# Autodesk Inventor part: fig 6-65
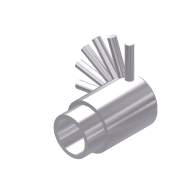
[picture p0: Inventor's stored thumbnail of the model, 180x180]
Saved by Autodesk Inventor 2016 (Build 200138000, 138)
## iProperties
Shininess: 77.0
Angle Display Precision: 2
Document Length Units: 11269
Document Angle Units: 11279
Document Time Units: 11290
Document Mass Units: 11283
Document Length Units Precision: 3
Document Angle Units Precision: 2
Compacted: True
Created: 2001-12
Part Number: fig 6-65
Document SubType Name: Modeling
Designer: Renu Muthoo
Density: 1 g/cm^3
Material: Generic
Appearance: Metal-AL-6061 (Polished)
Density: 0.0
Volumn: 0.0
Area: 0.0
PropertySet Name: Model Information
Control State: 0
Master: False
Checked Out: False
Author: Renu Muthoo
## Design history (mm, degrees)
sketch "Sketch2"
  geometry: L1 (-9.573, -4.327)-(-9.573, -5.327); L2 (-9.573, -5.327)-(-4.573, -5.327); L3 (-4.573, -5.327)-(-4.573, -6.327); L4 (-4.573, -6.327)-(9.427, -6.327); L5 (9.427, -6.327)-(10.427, -5.327); L6 (10.427, -5.327)-(10.427, -4.327); L7 (10.427, -4.327)-(-9.573, -4.327); L8 (-13.687, -0.327)-(14, -0.327)
  constraints: 16 end point, 5 parallel, 1 perpendicular, 1 vertical
  dimensions: "d9" = 20 distance of L6.end L1.start; "d10" = 5 distance of L1.end L2.end; "d11" = 12 diameter of L4 L8; "d12" = 10 diameter of L2 L8; "d13" = 8 diameter of L7 L8; "d14" = 45 deg angle of L5 L4; "d15" = 1 horizontal distance of L5.end L4.end
revolve "Revolution2" sketch "Sketch2" stored, may be unused: angle "d16" = 90 deg
workplane "Work Plane1"
workplane "Work Plane2"
sketch "Sketch3"
  geometry: L1 (-4, 8)-(4, 8) reference; C1 r 1 at (-0.098, 5)
  constraints: 1 centre point
  dimensions: "d18" = 3 distance from line of L1 C1.centre; "d19" = 2 diameter of C1
extrude "Extrusion1" join sketch "Sketch3" distance "d20" = 10; taper "d21" = 0 deg
pattern_circular "Circular Pattern3" dims angle "d29" = 20 deg
body "Solid1"
other parameters: "d17" = -1
